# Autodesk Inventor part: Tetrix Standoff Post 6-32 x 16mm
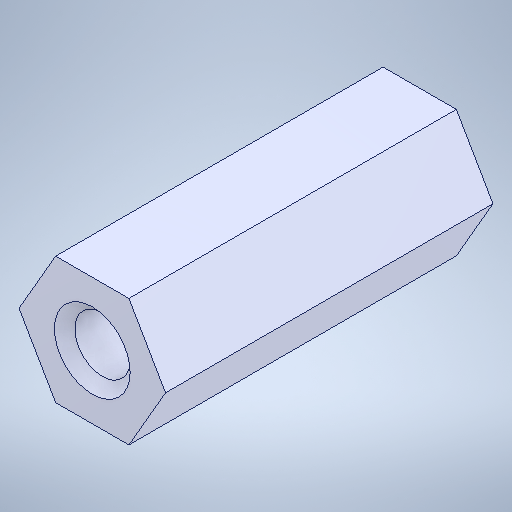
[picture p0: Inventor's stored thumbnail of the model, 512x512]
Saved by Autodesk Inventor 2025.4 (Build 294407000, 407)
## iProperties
Created: 2021-10
Part Number: Tetrix Standoff Post 6-32 x 16mm
Material: Genérico
Document SubType Name: Modeling
Designer: usuario
Density: 1 g/cm^3
Appearance: Valor por defecto
Author: usuario
Sending System: SolidWorks 2016
Last Author: LENOVO
Last Saved: 2021-10-26
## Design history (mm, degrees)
chamfer "Chamfer1"
node "Sólido1"
